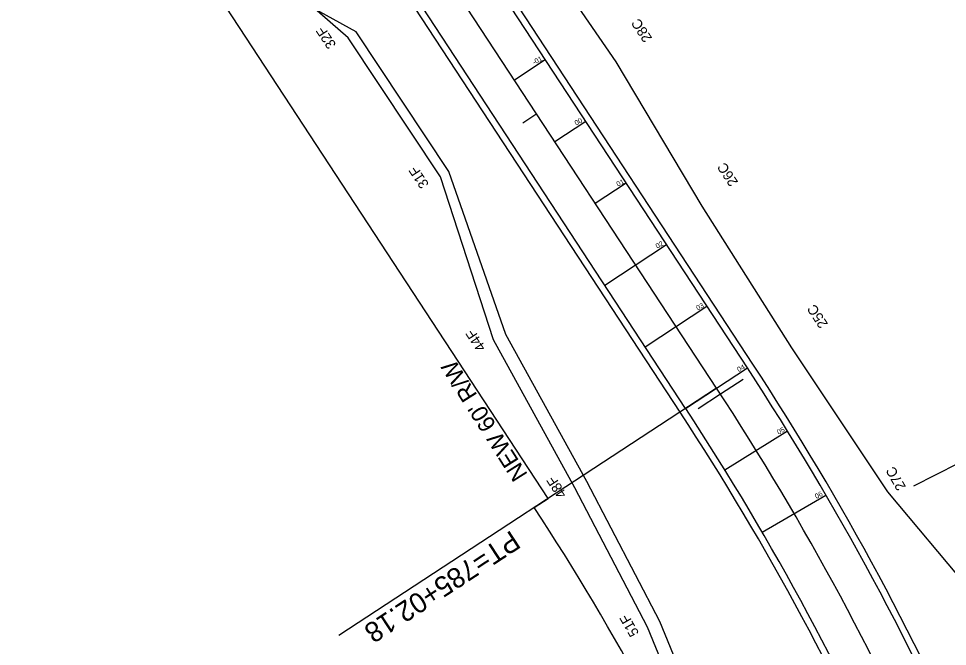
# Model space of a CAD drawing. Extents: x 1551641 to 1624343, y 1119533 to 1136600.
# Drawn here: x 1552624.3 to 1552901.3, y 1133922.6 to 1134110 of the extents above; entities that cross this region are included whole.
import ezdxf

# ---------------------------------------------------------------- set-up
doc = ezdxf.new("R2010")
doc.units = 0
for name, color, linetype in [('RD_HC_CL_Rel', 7, 'Continuous'), ('RD_HC_Data', 7, 'Continuous'), ('RD_HC_Data_Tic', 7, 'Continuous'), ('RD_PD_ALT1_TX', 7, 'Continuous'), ('RD_PD_CstnLmt', 7, 'Continuous'), ('RD_PD_CstnLmt_TX', 7, 'Continuous'), ('RD_PD_DR_ErosCtrl', 7, 'Continuous'), ('RD_PD_Final_TrvlWay', 7, 'Continuous'), ('RD_PD_PaveShd', 7, 'Continuous'), ('RD_PD_RW', 7, 'Continuous')]:
    doc.layers.add(name, color=color, linetype=linetype)

msp = doc.modelspace()

# ---------------------------------------------------------------- linework, layer by layer
at = {"layer": 'RD_HC_CL_Rel'}
msp.add_line((1552832.44, 1133999.68), (1552472.39, 1134549.2), dxfattribs=at)
msp.add_arc((1552135.69, 1133543.15), 833, 23.29239, 33.23375, dxfattribs=at)
at = {"layer": 'RD_HC_Data'}
msp.add_line((1552832.44, 1133999.68), (1552719.79, 1133925.87), dxfattribs=at)
at = {"layer": 'RD_HC_Data_Tic'}
for p, q in [((1552778.84, 1134081.5), (1552774.65, 1134078.76)), ((1552840.34, 1134002.22), (1552833.64, 1133997.85)), ((1552833.64, 1133997.85), (1552826.94, 1133993.49))]:
    msp.add_line(p, q, dxfattribs=at)
at = {"layer": 'RD_PD_ALT1_TX'}
for p, q in [((1552772.16, 1134091.69), (1552781.36, 1134097.72)), ((1552784.22, 1134073.29), (1552793.42, 1134079.32)), ((1552796.27, 1134054.89), (1552805.47, 1134060.92)), ((1552799.13, 1134030.46), (1552817.53, 1134042.51)), ((1552811.19, 1134012.06), (1552829.59, 1134024.11)), ((1552823.24, 1133993.65), (1552841.65, 1134005.71)), ((1552834.9, 1133975.34), (1552853.61, 1133986.91)), ((1552846.07, 1133956.72), (1552865.08, 1133967.79))]:
    msp.add_line(p, q, dxfattribs=at)
at = {"layer": 'RD_PD_CstnLmt'}
for p, q in [((1552802.49, 1134097), (1552774.24, 1134138.26)), ((1552725, 1134106), (1552709.32, 1134114.6)), ((1552752.66, 1134064.35), (1552725, 1134106)), ((1552828.13, 1134054.02), (1552802.49, 1134097)), ((1552769.61, 1134015.68), (1552752.66, 1134064.35)), ((1552854.91, 1134011.71), (1552828.13, 1134054.02)), ((1552793.73, 1133971.85), (1552769.61, 1134015.68)), ((1552883.55, 1133968.76), (1552854.91, 1134011.71)), ((1552815.52, 1133930.05), (1552793.73, 1133971.85)), ((1552917.57, 1133927.97), (1552883.55, 1133968.76)), ((1552833.37, 1133886.53), (1552815.52, 1133930.05))]:
    msp.add_line(p, q, dxfattribs=at)
at = {"layer": 'RD_PD_DR_ErosCtrl'}
for p, q in [((1552722.56, 1134104.25), (1552683.53, 1134138.41)), ((1552750.16, 1134062.69), (1552722.56, 1134104.25)), ((1552765.93, 1134014.08), (1552750.16, 1134062.69)), ((1552790.2, 1133969.97), (1552765.93, 1134014.08)), ((1552811.89, 1133928.36), (1552790.2, 1133969.97)), ((1552829.66, 1133885.02), (1552811.89, 1133928.36))]:
    msp.add_line(p, q, dxfattribs=at)
at = {"layer": 'RD_PD_Final_TrvlWay'}
for p, q in [((1552841.65, 1134005.71), (1552481.59, 1134555.23)), ((1552823.24, 1133993.65), (1552463.19, 1134543.17))]:
    msp.add_line(p, q, dxfattribs=at)
for radius in [844, 822]:
    msp.add_arc((1552135.69, 1133543.15), radius, 23.29239, 33.23375, dxfattribs=at)
at = {"layer": 'RD_PD_PaveShd'}
for p, q in [((1552843.32, 1134006.81), (1552718.03, 1134198.02)), ((1552821.57, 1133992.56), (1552697.38, 1134182.1))]:
    msp.add_line(p, q, dxfattribs=at)
for radius in [846, 820]:
    msp.add_arc((1552135.69, 1133543.15), radius, 23.29239, 33.23375, dxfattribs=at)
at = {"layer": 'RD_PD_RW'}
for p, q in [((1552782.26, 1133966.8), (1552660.14, 1134153.17)), ((1552891.26, 1133970.55), (1552904.57, 1133977.32)), ((1552778.08, 1133964.06), (1552782.26, 1133966.8))]:
    msp.add_line(p, q, dxfattribs=at)
msp.add_arc((1552135.69, 1133543.15), 768, 23.29239, 33.23375, dxfattribs=at)

# ---------------------------------------------------------------- texts
at = {"layer": 'RD_HC_Data'}
msp.add_text('PT=785+02.18', height=6, rotation=213.2337, dxfattribs=at).set_placement((1552771.24, 1133957.46))
at = {"layer": 'RD_PD_ALT1_TX'}
for s, p in [('-01', (1552778.02, 1134096.12)), ('00', (1552790.58, 1134078.02)), ('01', (1552803.05, 1134059.76)), ('02', (1552814.75, 1134041.29)), ('03', (1552826.82, 1134022.81)), ('04', (1552839.06, 1134004.44)), ('05', (1552850.95, 1133985.77)), ('06', (1552862.24, 1133966.61))]:
    msp.add_text(s, height=1.5, rotation=27.7864, dxfattribs=at).set_placement(p)
at = {"layer": 'RD_PD_CstnLmt_TX'}
for s, rotation, p in [('28C', 123.2337, (1552813.36, 1134104.12)), ('32F', 123.2337, (1552719.14, 1134102.17)), ('26C', 123.2337, (1552839, 1134061.15)), ('31F', 123.2337, (1552746.8, 1134060.51)), ('25C', 123.0836, (1552865.8, 1134018.81)), ('44F', 123.2337, (1552763.76, 1134011.84)), ('27C', 119.6444, (1552889.02, 1133970.22)), ('48F', 123.0836, (1552787.87, 1133968.03)), ('51F', 119.6444, (1552809.43, 1133926.58))]:
    msp.add_text(s, height=3, rotation=rotation, dxfattribs=at).set_placement(p)
at = {"layer": 'RD_PD_RW'}
msp.add_text("NEW 60' R/W", height=5, rotation=122.3587, dxfattribs=at).set_placement((1552776.26, 1133973.92))

doc.saveas('drawing.dxf')
